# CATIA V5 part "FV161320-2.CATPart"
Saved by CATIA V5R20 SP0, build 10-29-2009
Part number: FV161320-2
Revision: ANY
Definition: UNKNOWN
Nomenclature: FV161320-2
Source: Unknown
Bounding box of the stored display mesh (mm): x -6.337 to 6.337, y -15.5 to 0, z -6.5 to 6.5
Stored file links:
  C:\Users\Utente\Desktop\IO LAVORO\3D X SITO CF\CUMSA\3D files FV\FV 161320\FV161320-2.CATPart
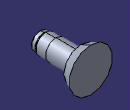
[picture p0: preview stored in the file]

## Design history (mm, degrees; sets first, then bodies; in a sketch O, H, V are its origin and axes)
Body1 "Chaflán1" (main body)
  Solid1: solid without history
